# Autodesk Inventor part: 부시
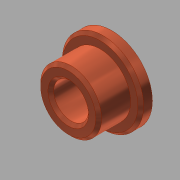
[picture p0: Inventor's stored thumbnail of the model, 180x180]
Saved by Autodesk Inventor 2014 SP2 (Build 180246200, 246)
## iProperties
Created: 2016-02
Part Number: 부시
Material: 강철, 연강
Document SubType Name: Modeling
Designer: test
Density: 1 g/cm^3
Appearance: 금속 1400F 열
Author: test
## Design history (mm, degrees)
sketch "스케치1"
  geometry: C1 r 14 at (0, 0); C2 r 10.5 at (0, 0); 1 further point
  constraints: 2 centre point, 2 coincident
  dimensions: "d0" = 28 diameter of C1; "d1" = 21 diameter of C2
extrude "돌출1" new body sketch "스케치1" distance "d2" = 4; taper "d3" = 0 deg
extrude "돌출2" join sketch "스케치1" distance "d4" = 11; taper "d5" = 0 deg
hole "구멍1" diameter "d8" = 12; stored, may be unused: countersink angle "d12" = 90 deg, drill point angle "d14" = 118 deg; dims "d6" = 10, "d7" = 10, "d9" = 6, "d10" = 4, "d11" = 2, "d13" = 8
chamfer "모따기1" distance "d15" = 1; stored, may be unused: second distance "d16" = 2, angle "d17" = 45 deg
chamfer "모따기2" distance "d18" = 1; stored, may be unused: second distance "d19" = 2, angle "d20" = 45 deg
node "솔리드1"
